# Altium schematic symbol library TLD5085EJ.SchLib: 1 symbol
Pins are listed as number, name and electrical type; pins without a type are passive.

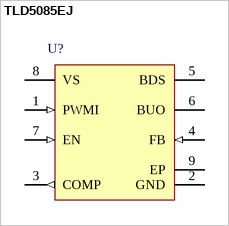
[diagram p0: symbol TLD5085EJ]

## TLD5085EJ
designator U?
1.8 A DC/DC Step-Down Converter, 4.75 to 45 V, -40 to 150 degC, PG-DSO-8-27, Reel, Pb-free; Manufacturer: Infineon; PartNumber: TLD5085EJ; Green: TRUE; Topology: DC-DC Buck; VS (max): 45 V; VS (min): 4.75 V
footprint INF-PG-DSO-8-27_N (SOP, 8-Leads, Body 4.9x3.9mm, Pitch 1.27mm, Thermal Pad 3.2x2.85mm, IPC Medium Density)
footprint INF-PG-DSO-8-27_L (SOP, 8-Leads, Body 4.9x3.9mm, Pitch 1.27mm, Thermal Pad 3.2x2.85mm, IPC High Density)
footprint INF-PG-DSO-8-27_M (SOP, 8-Leads, Body 4.9x3.9mm, Pitch 1.27mm, Thermal Pad 3.2x2.85mm, IPC Low Density)
pins: 1 PWMI (in) "PWM Input for; Provides LED dimming option. If not used connect to VS.", 2 GND (power) "Ground; Connect to system ground.", 3 COMP (out) "Compensation Input; Frequency compensation for regulation loop stability. Connect R and C network to pin for stability.", 4 FB (in) "Feedback Input; Connect a defined power resistor (RFB=0.6V/ILED) to get the needed LED output current. For adjustable output voltages connect this pin via a voltage divider in parallel to the output capacitor.", 5 BDS (power) "Buck Driver Supply Input; Connect the bootstrap capacitor between this pin and pin BUO.", 6 BUO (oe) "Buck Switch Output; Source of the integrated power-switch. Connect directly to the cathode of external freewheeling diode and the buck circuit inductance.", 7 EN (in) "Enable Input; Apply logic high signal to enable the device. A pull down resistor is integrated.", 8 VS (power) "Supply Voltage Input; Connect to supply voltage source.", 9 EP (power) "Exposed Pad; Connect to heatsink area and GND by low inductance wiring."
